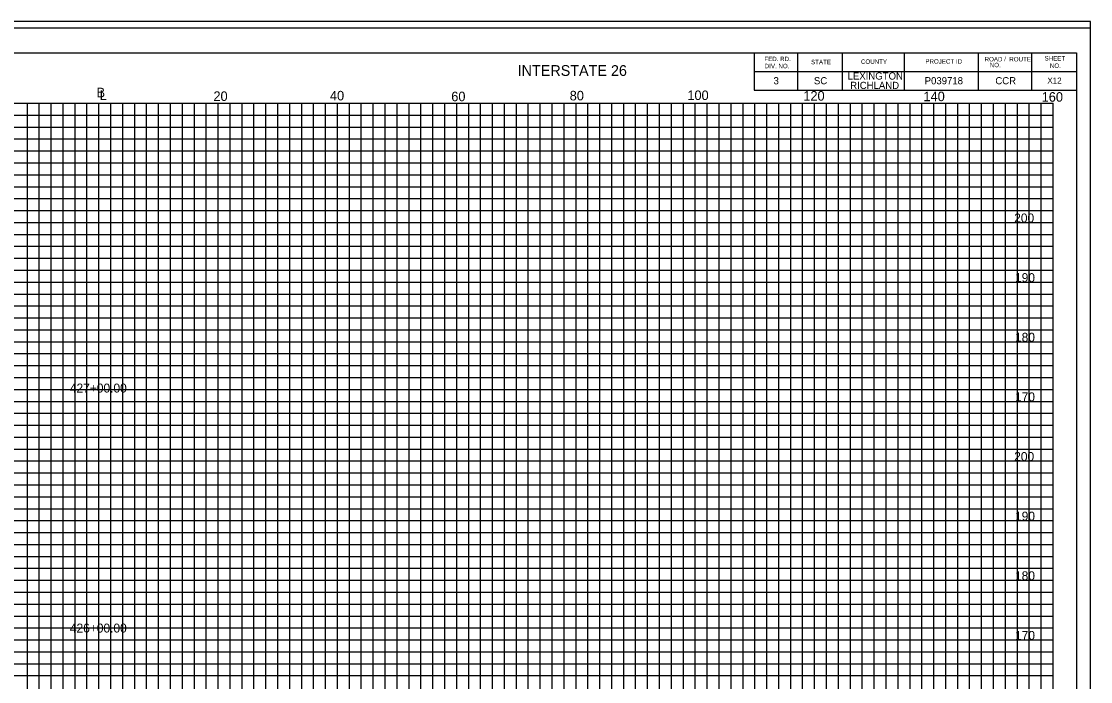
# Model space of a CAD drawing. Extents: x 967 to 1746, y 964 to 7904.
# Drawn here: x 1147 to 1326.3, y 3313 to 3423.7 of the extents above; entities that cross this region are included whole.
import ezdxf

# ---------------------------------------------------------------- set-up
doc = ezdxf.new("R2010")
doc.units = 0
for name, color, linetype in [('Default', 7, 'Continuous'), ('RD_SHT_Bndy', 7, 'Continuous'), ('RD_SHT_IplotShp', 7, 'Continuous'), ('RD_SHT_MjGrid', 7, 'Continuous'), ('RD_SHT_MnGrid', 7, 'Continuous'), ('RD_SHT_TX', 7, 'Continuous'), ('RD_Sketch1', 7, 'Continuous')]:
    doc.layers.add(name, color=color, linetype=linetype)

msp = doc.modelspace()

# ---------------------------------------------------------------- linework, layer by layer
at = {"layer": 'RD_SHT_Bndy'}
for p, q in [((996.11, 3418.46), (1323.89, 3418.46)), ((1269.89, 3418.46), (1269.89, 3412.21)), ((1277.14, 3418.46), (1277.14, 3412.21)), ((1284.64, 3418.46), (1284.64, 3412.21)), ((1295, 3418.46), (1295, 3412.21)), ((1307.43, 3418.46), (1307.43, 3412.21)), ((1316.39, 3418.46), (1316.39, 3412.21)), ((1323.89, 3418.46), (1323.89, 3208.98)), ((1269.89, 3415.33), (1323.89, 3415.33)), ((1269.89, 3412.21), (1323.89, 3412.21))]:
    msp.add_line(p, q, dxfattribs=at)
at = {"layer": 'RD_SHT_IplotShp'}
for points in [[(967.41, 3203.72), (1326.28, 3203.72), (1326.28, 3423.72), (967.41, 3423.72)], [(988.52, 3204.84), (1326.28, 3204.84), (1326.28, 3422.6), (988.52, 3422.6)]]:
    msp.add_lwpolyline(points, close=True, dxfattribs=at)
at = {"layer": 'RD_SHT_MjGrid'}
for p, q in [((1000, 3410), (1320, 3410)), ((1150, 3240), (1150, 3410)), ((1160, 3240), (1160, 3410)), ((1170, 3240), (1170, 3410)), ((1180, 3240), (1180, 3410)), ((1190, 3240), (1190, 3410)), ((1200, 3240), (1200, 3410)), ((1210, 3240), (1210, 3410)), ((1220, 3240), (1220, 3410)), ((1230, 3240), (1230, 3410)), ((1240, 3240), (1240, 3410)), ((1250, 3240), (1250, 3410)), ((1260, 3240), (1260, 3410)), ((1270, 3240), (1270, 3410)), ((1280, 3240), (1280, 3410)), ((1290, 3240), (1290, 3410)), ((1300, 3240), (1300, 3410)), ((1310, 3240), (1310, 3410)), ((1320, 3240), (1320, 3410)), ((1000, 3400), (1320, 3400)), ((1000, 3390), (1320, 3390)), ((1000, 3380), (1320, 3380)), ((1000, 3370), (1320, 3370)), ((1000, 3360), (1320, 3360)), ((1000, 3350), (1320, 3350)), ((1000, 3340), (1320, 3340)), ((1000, 3330), (1320, 3330)), ((1000, 3320), (1320, 3320))]:
    msp.add_line(p, q, dxfattribs=at)
at = {"layer": 'RD_SHT_MnGrid'}
for p, q in [((1148, 3240), (1148, 3410)), ((1152, 3240), (1152, 3410)), ((1154, 3240), (1154, 3410)), ((1156, 3240), (1156, 3410)), ((1158, 3240), (1158, 3410)), ((1162, 3240), (1162, 3410)), ((1164, 3240), (1164, 3410)), ((1166, 3240), (1166, 3410)), ((1168, 3240), (1168, 3410)), ((1172, 3240), (1172, 3410)), ((1174, 3240), (1174, 3410)), ((1176, 3240), (1176, 3410)), ((1178, 3240), (1178, 3410)), ((1182, 3240), (1182, 3410)), ((1184, 3240), (1184, 3410)), ((1186, 3240), (1186, 3410)), ((1188, 3240), (1188, 3410)), ((1192, 3240), (1192, 3410)), ((1194, 3240), (1194, 3410)), ((1196, 3240), (1196, 3410)), ((1198, 3240), (1198, 3410)), ((1202, 3240), (1202, 3410)), ((1204, 3240), (1204, 3410)), ((1206, 3240), (1206, 3410)), ((1208, 3240), (1208, 3410)), ((1212, 3240), (1212, 3410)), ((1214, 3240), (1214, 3410)), ((1216, 3240), (1216, 3410)), ((1218, 3240), (1218, 3410)), ((1222, 3240), (1222, 3410)), ((1224, 3240), (1224, 3410)), ((1226, 3240), (1226, 3410)), ((1228, 3240), (1228, 3410)), ((1232, 3240), (1232, 3410)), ((1234, 3240), (1234, 3410)), ((1236, 3240), (1236, 3410)), ((1238, 3240), (1238, 3410)), ((1242, 3240), (1242, 3410)), ((1244, 3240), (1244, 3410)), ((1246, 3240), (1246, 3410)), ((1248, 3240), (1248, 3410)), ((1252, 3240), (1252, 3410)), ((1254, 3240), (1254, 3410)), ((1256, 3240), (1256, 3410)), ((1258, 3240), (1258, 3410)), ((1262, 3240), (1262, 3410)), ((1264, 3240), (1264, 3410)), ((1266, 3240), (1266, 3410)), ((1268, 3240), (1268, 3410)), ((1272, 3240), (1272, 3410)), ((1274, 3240), (1274, 3410)), ((1276, 3240), (1276, 3410)), ((1278, 3240), (1278, 3410)), ((1282, 3240), (1282, 3410)), ((1284, 3240), (1284, 3410)), ((1286, 3240), (1286, 3410)), ((1288, 3240), (1288, 3410)), ((1292, 3240), (1292, 3410)), ((1294, 3240), (1294, 3410)), ((1296, 3240), (1296, 3410)), ((1298, 3240), (1298, 3410)), ((1302, 3240), (1302, 3410)), ((1304, 3240), (1304, 3410)), ((1306, 3240), (1306, 3410)), ((1308, 3240), (1308, 3410)), ((1312, 3240), (1312, 3410)), ((1314, 3240), (1314, 3410)), ((1316, 3240), (1316, 3410)), ((1318, 3240), (1318, 3410)), ((1000, 3408), (1320, 3408)), ((1000, 3406), (1320, 3406)), ((1000, 3404), (1320, 3404)), ((1000, 3402), (1320, 3402)), ((1000, 3398), (1320, 3398)), ((1000, 3396), (1320, 3396)), ((1000, 3394), (1320, 3394)), ((1000, 3392), (1320, 3392)), ((1000, 3388), (1320, 3388)), ((1000, 3386), (1320, 3386)), ((1000, 3384), (1320, 3384)), ((1000, 3382), (1320, 3382)), ((1000, 3378), (1320, 3378)), ((1000, 3376), (1320, 3376)), ((1000, 3374), (1320, 3374)), ((1000, 3372), (1320, 3372)), ((1000, 3368), (1320, 3368)), ((1000, 3366), (1320, 3366)), ((1000, 3364), (1320, 3364)), ((1000, 3362), (1320, 3362)), ((1000, 3358), (1320, 3358)), ((1000, 3356), (1320, 3356)), ((1000, 3354), (1320, 3354)), ((1000, 3352), (1320, 3352)), ((1000, 3348), (1320, 3348)), ((1000, 3346), (1320, 3346)), ((1000, 3344), (1320, 3344)), ((1000, 3342), (1320, 3342)), ((1000, 3338), (1320, 3338)), ((1000, 3336), (1320, 3336)), ((1000, 3334), (1320, 3334)), ((1000, 3332), (1320, 3332)), ((1000, 3328), (1320, 3328)), ((1000, 3326), (1320, 3326)), ((1000, 3324), (1320, 3324)), ((1000, 3322), (1320, 3322)), ((1000, 3318), (1320, 3318)), ((1000, 3316), (1320, 3316)), ((1000, 3314), (1320, 3314))]:
    msp.add_line(p, q, dxfattribs=at)
at = {"layer": 'RD_Sketch1'}
msp.add_lwpolyline([(967.41, 3203.72), (1326.28, 3203.72), (1326.28, 3423.72), (967.41, 3423.72)], close=True, dxfattribs=at)

# ---------------------------------------------------------------- texts
at = {"layer": 'Default'}
for s, height, p in [('X12', 1, (1319.04, 3413.3)), ('200', 1.5, (1313.47, 3390)), ('190', 1.5, (1313.61, 3380)), ('180', 1.5, (1313.61, 3370)), ('427+00.00', 1.5, (1155.13, 3361.48)), ('170', 1.5, (1313.61, 3360)), ('200', 1.5, (1313.47, 3350)), ('190', 1.5, (1313.61, 3340)), ('180', 1.5, (1313.61, 3330)), ('426+00.00', 1.5, (1155.13, 3321.23)), ('170', 1.5, (1313.61, 3320))]:
    msp.add_text(s, height=height, dxfattribs=at).set_placement(p)
at = {"layer": 'RD_SHT_TX'}
for s, height, p in [('FED. RD.', 0.75, (1271.58, 3417.05)), ('STATE', 0.75, (1279.41, 3416.53)), ('COUNTY', 0.75, (1287.78, 3416.59)), ('PROJECT ID', 0.75, (1298.58, 3416.63)), ('ROAD /  ROUTE', 0.75, (1308.51, 3417.01)), ('SHEET', 0.75, (1318.56, 3417.16)), ('DIV. NO.', 0.75, (1271.64, 3415.86)), ('   NO.', 0.75, (1308.51, 3416.03)), ('NO.', 0.75, (1319.45, 3415.91)), ('3', 1.2, (1273.12, 3413.17)), ('SC', 1.2, (1279.89, 3413.17)), ('LEXINGTON', 1.2, (1285.54, 3413.96)), ('RICHLAND', 1.2, (1285.97, 3412.39)), ('P039718', 1.2, (1298.46, 3413.17)), ('CCR', 1.2, (1310.31, 3413.17)), ('B', 1.6, (1159.61, 3410.99)), ('L', 1.6, (1160.12, 3410.54)), ('20', 1.6, (1179.2, 3410.38)), ('40', 1.6, (1198.74, 3410.47)), ('60', 1.6, (1219.08, 3410.33)), ('80', 1.6, (1238.94, 3410.47)), ('100', 1.6, (1258.67, 3410.53)), ('120', 1.6, (1278.11, 3410.43)), ('140', 1.6, (1298.26, 3410.34)), ('160', 1.6, (1318.08, 3410.25))]:
    msp.add_text(s, height=height, dxfattribs=at).set_placement(p)
msp.add_text('INTERSTATE 26', height=1.8, rotation=0, dxfattribs=at).set_placement((1230.21, 3414.58))

doc.saveas('drawing.dxf')
